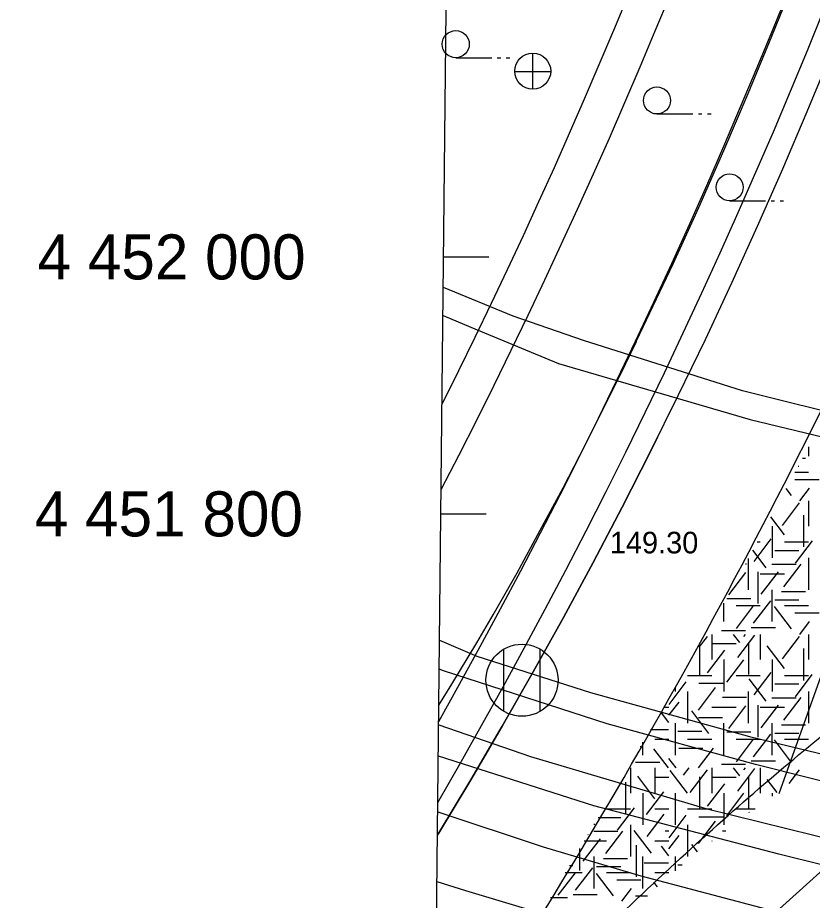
# Model space of a CAD drawing. Extents: x 419677 to 421689, y 4450851 to 4452923.
# Drawn here: x 420146.99 to 420191.07, y 4451964.28 to 4452013.28 of the extents above; entities that cross this region are included whole.
import ezdxf

# ---------------------------------------------------------------- set-up
doc = ezdxf.new("R2010")
doc.units = 0
for name, color, linetype in [('AA_HH', 7, 'Continuous'), ('Level 15', 7, 'Continuous'), ('Level 41', 7, 'Continuous'), ('Level 53', 7, 'Continuous'), ('Level 62', 7, 'Continuous'), ('Level 7', 7, 'Continuous')]:
    doc.layers.add(name, color=color, linetype=linetype)

msp = doc.modelspace()

# ---------------------------------------------------------------- linework, layer by layer
at = {"layer": 'AA_HH'}
for p, q in [((420171.29, 4452011.059), (420173.29, 4452011.059)), ((420173.59, 4452011.059), (420173.79, 4452011.059)), ((420174.09, 4452011.059), (420174.29, 4452011.059)), ((420175.574, 4452009.304), (420175.574, 4452011.304)), ((420174.554, 4452010.294), (420176.554, 4452010.294)), ((420182.45, 4452007.935), (420184.45, 4452007.935)), ((420184.75, 4452007.935), (420184.95, 4452007.935)), ((420185.25, 4452007.935), (420185.45, 4452007.935)), ((420186.481, 4452003.116), (420188.481, 4452003.116)), ((420188.781, 4452003.116), (420188.981, 4452003.116)), ((420189.281, 4452003.116), (420189.481, 4452003.116)), ((420170.62, 4452000), (420173.12, 4452000)), ((420170.469, 4451985.736), (420172.969, 4451985.736)), ((420173.965, 4451974.773), (420173.965, 4451978.234)), ((420175.965, 4451974.773), (420175.965, 4451978.234))]:
    msp.add_line(p, q, dxfattribs=at)
msp.add_lwpolyline([(420173.096, 4452234.536), (420705.284, 4452228.915), (420698.004, 4451534.891), (420165.768, 4451540.511)], close=True, dxfattribs=at)
for points in [[(420187.203, 4451992.557), (420178.373, 4451995.36), (420174.466, 4451996.716), (420170.602, 4451998.293)], [(420170.586, 4451996.757), (420172.131, 4451996.1), (420176.994, 4451994.079), (420187.618, 4451990.981)], [(420208.49, 4451987.848), (420200.392, 4451989.268), (420187.203, 4451992.557)], [(420187.618, 4451990.981), (420198.83, 4451988.282), (420204.042, 4451987.253), (420208.477, 4451986.632)], [(420170.395, 4451978.717), (420172.464, 4451977.845)], [(420172.464, 4451977.845), (420178.769, 4451975.819)], [(420178.769, 4451975.819), (420187.591, 4451973.382), (420198.769, 4451970.67), (420203.694, 4451969.685), (420203.855, 4451969.575), (420203.873, 4451969.498), (420203.829, 4451969.249), (420202.943, 4451968.135), (420202.702, 4451968.102), (420187.925, 4451971.818), (420179.685, 4451974.079), (420170.604, 4451977.031), (420170.378, 4451977.116)], [(420170.346, 4451974.034), (420175.443, 4451972.262), (420185.168, 4451969.381), (420195.648, 4451966.791), (420199.48, 4451965.936), (420200.521, 4451965.653), (420200.873, 4451965.482), (420200.86, 4451965.328), (420200.779, 4451965.109), (420200.125, 4451964.605), (420199.68, 4451964.413), (420199.276, 4451964.355), (420189.216, 4451966.84), (420178.959, 4451969.531)], [(420178.959, 4451969.531), (420170.327, 4451972.292)], [(420170.294, 4451969.192), (420176.139, 4451967.249), (420181.55, 4451965.648), (420190.183, 4451963.368), (420196.492, 4451961.996), (420196.577, 4451961.946), (420196.689, 4451961.78), (420196.627, 4451961.561), (420195.666, 4451959.622)], [(420172.68, 4451928.596), (420176.129, 4451935.418), (420177.785, 4451938.644), (420180.669, 4451943.689), (420183.638, 4451948.265), (420186.589, 4451952.666), (420190.119, 4451957.419), (420191.107, 4451958.75), (420191.136, 4451958.895), (420191.153, 4451959.063), (420191.123, 4451959.248), (420191.039, 4451959.379), (420190.981, 4451959.447), (420190.818, 4451959.577), (420182.51, 4451961.605), (420171.851, 4451964.82), (420170.254, 4451965.318)]]:
    msp.add_lwpolyline(points, dxfattribs=at)
for centre, radius in [((420171.29, 4452011.809), 0.75), ((420175.559, 4452010.312), 1), ((420182.45, 4452008.685), 0.75), ((420186.481, 4452003.866), 0.75), ((420174.965, 4451976.503), 2)]:
    msp.add_circle(centre, radius, dxfattribs=at)
at = {"layer": 'Level 15'}
msp.add_lwpolyline([(420240.251, 4451968.677), (420239.949, 4451966.602), (420239.949, 4451966.602), (420231.732, 4451917.739), (420240.801, 4451915.152), (420236.082, 4451892.337), (420229.855, 4451894.289), (420220.346, 4451839.788), (420214.729, 4451827.789), (420207.555, 4451825.12), (420146.986, 4451843.868), (420162.882, 4451888.718), (420178.991, 4451939.954), (420183.444, 4451958.583), (420204.023, 4451977.132), (420216.413, 4451977.263), (420240.251, 4451968.677)], dxfattribs=at)
at = {"layer": 'Level 41'}
for p, q in [((420190.866, 4451989.456), (420190.866, 4451988.935)), ((420190.531, 4451988.837), (420190.7, 4451988.837)), ((420190.105, 4451988.051), (420190.866, 4451988.051)), ((420190.284, 4451988.381), (420190.326, 4451988.381)), ((420190.102, 4451987.644), (420191.445, 4451987.644)), ((420189.919, 4451986.756), (420189.618, 4451987.151)), ((420190.385, 4451986.458), (420190.922, 4451987.164)), ((420189.413, 4451985.095), (420190.362, 4451986.345)), ((420190.866, 4451986.458), (420190.866, 4451985.06)), ((420189.52, 4451984.569), (420188.761, 4451985.567)), ((420190.584, 4451985.67), (420190.584, 4451983.903)), ((420188.852, 4451985.06), (420188.852, 4451983.293)), ((420187.842, 4451983.097), (420188.793, 4451984.346)), ((420188.008, 4451984.176), (420188.18, 4451984.176)), ((420189.523, 4451984.176), (420190.866, 4451984.176)), ((420190.133, 4451982.992), (420191.082, 4451984.242)), ((420188.508, 4451982.747), (420187.764, 4451983.725)), ((420188.983, 4451983.706), (420190.326, 4451983.706)), ((420187.509, 4451983.254), (420187.509, 4451981.526)), ((420190.866, 4451983.293), (420190.866, 4451981.526)), ((420187.355, 4451982.969), (420187.424, 4451982.969)), ((420188.823, 4451982.936), (420190.166, 4451982.936)), ((420189.493, 4451981.695), (420190.443, 4451982.945)), ((420186.43, 4451981.239), (420187.38, 4451982.489)), ((420188.041, 4451982.521), (420188.041, 4451980.753)), ((420188.18, 4451982.409), (420189.523, 4451982.409)), ((420188.241, 4451981.275), (420189.19, 4451982.524)), ((420188.852, 4451979.758), (420188.852, 4451981.526)), ((420189.357, 4451981.428), (420190.7, 4451981.428)), ((420186.166, 4451979.758), (420186.166, 4451980.772)), ((420186.32, 4451981.043), (420187.663, 4451981.043)), ((420187.816, 4451979.661), (420188.765, 4451980.911)), ((420188.983, 4451980.972), (420190.326, 4451980.972)), ((420186.837, 4451980.642), (420188.18, 4451980.642)), ((420186.856, 4451979.382), (420187.805, 4451980.631)), ((420189.919, 4451979.347), (420188.969, 4451980.596)), ((420189.523, 4451980.642), (420190.866, 4451980.642)), ((420190.102, 4451980.235), (420191.445, 4451980.235)), ((420190.385, 4451979.049), (420190.922, 4451979.755)), ((420186.027, 4451979.255), (420187.37, 4451979.255)), ((420187.679, 4451979.43), (420189.022, 4451979.43)), ((420184.796, 4451978.34), (420185.248, 4451978.936)), ((420185.494, 4451979.049), (420185.494, 4451977.651)), ((420187.043, 4451978.597), (420186.699, 4451979.049)), ((420186.936, 4451977.755), (420187.886, 4451979.005)), ((420187.269, 4451978.929), (420187.36, 4451979.049)), ((420188.18, 4451979.049), (420188.18, 4451977.651)), ((420189.413, 4451977.686), (420190.362, 4451978.936)), ((420190.866, 4451979.049), (420190.866, 4451977.651)), ((420184.819, 4451978.38), (420184.819, 4451976.78)), ((420185.494, 4451978.535), (420186.837, 4451978.535)), ((420187.536, 4451978.582), (420187.536, 4451976.815)), ((420189.52, 4451977.16), (420188.571, 4451978.409)), ((420190.584, 4451978.261), (420190.584, 4451976.494)), ((420185.259, 4451976.914), (420186.208, 4451978.164)), ((420186.166, 4451977.651), (420186.166, 4451975.884)), ((420186.325, 4451976.389), (420187.274, 4451977.639)), ((420188.852, 4451977.651), (420188.852, 4451975.884)), ((420184.151, 4451976.767), (420185.494, 4451976.767)), ((420186.837, 4451976.767), (420188.18, 4451976.767)), ((420187.842, 4451975.688), (420188.793, 4451976.937)), ((420189.523, 4451976.767), (420190.866, 4451976.767)), ((420190.133, 4451975.583), (420191.069, 4451976.815)), ((420183.128, 4451975.163), (420184.077, 4451976.412)), ((420184.775, 4451976.333), (420186.118, 4451976.333)), ((420188.508, 4451975.338), (420187.558, 4451976.587)), ((420188.983, 4451976.297), (420190.326, 4451976.297)), ((420183.48, 4451975.884), (420183.48, 4451976.123)), ((420184.151, 4451975.884), (420184.151, 4451974.117)), ((420184.753, 4451974.846), (420185.702, 4451976.096)), ((420187.509, 4451975.884), (420187.509, 4451974.117)), ((420190.866, 4451975.884), (420190.866, 4451974.117)), ((420183.118, 4451974.554), (420183.677, 4451975.29)), ((420186.081, 4451975.56), (420187.424, 4451975.56)), ((420188.823, 4451975.527), (420190.166, 4451975.527)), ((420189.493, 4451974.286), (420190.443, 4451975.536)), ((420182.813, 4451975), (420183.118, 4451975)), ((420185.338, 4451973.549), (420184.389, 4451974.799)), ((420185.494, 4451975), (420186.837, 4451975)), ((420186.43, 4451973.83), (420187.38, 4451975.08)), ((420188.041, 4451975.112), (420188.041, 4451973.344)), ((420188.18, 4451975), (420189.523, 4451975)), ((420188.241, 4451973.866), (420189.19, 4451975.115)), ((420183.118, 4451974.16), (420182.712, 4451974.694)), ((420184.748, 4451974.44), (420186.091, 4451974.44)), ((420183.48, 4451972.349), (420183.48, 4451974.117)), ((420186.166, 4451972.349), (420186.166, 4451974.117)), ((420188.852, 4451972.349), (420188.852, 4451974.117)), ((420189.357, 4451974.019), (420190.7, 4451974.019)), ((420182.086, 4451973.774), (420183.084, 4451973.774)), ((420183.603, 4451973.668), (420184.946, 4451973.668)), ((420186.32, 4451973.634), (420187.663, 4451973.634)), ((420187.816, 4451972.252), (420188.765, 4451973.502)), ((420188.983, 4451973.563), (420190.326, 4451973.563)), ((420181.523, 4451972.826), (420181.566, 4451972.826)), ((420181.659, 4451972.349), (420181.659, 4451973.055)), ((420182.33, 4451973.233), (420183.118, 4451973.233)), ((420184.151, 4451973.233), (420185.494, 4451973.233)), ((420186.837, 4451973.233), (420188.18, 4451973.233)), ((420186.856, 4451971.973), (420187.805, 4451973.222)), ((420189.919, 4451971.938), (420188.969, 4451973.187)), ((420189.523, 4451973.233), (420190.866, 4451973.233)), ((420183.089, 4451971.64), (420182.287, 4451972.696)), ((420183.657, 4451972.722), (420184.999, 4451972.722)), ((420184.765, 4451971.64), (420185.594, 4451972.731)), ((420181.262, 4451971.952), (420182.605, 4451971.952)), ((420183.512, 4451971.64), (420183.118, 4451972.158)), ((420186.027, 4451971.846), (420187.37, 4451971.846)), ((420187.679, 4451972.021), (420189.022, 4451972.021)), ((420180.987, 4451971.64), (420180.987, 4451970.242)), ((420182.33, 4451971.64), (420182.33, 4451970.242)), ((420182.33, 4451971.64), (420182.33, 4451970.242)), ((420184.139, 4451970.242), (420183.19, 4451971.492)), ((420183.928, 4451971.223), (420184.245, 4451971.64)), ((420184.299, 4451970.277), (420185.248, 4451971.527)), ((420185.494, 4451971.64), (420185.494, 4451970.242)), ((420187.043, 4451971.188), (420186.699, 4451971.64)), ((420186.936, 4451970.346), (420187.886, 4451971.596)), ((420187.269, 4451971.52), (420187.36, 4451971.64)), ((420188.18, 4451971.64), (420188.18, 4451970.242)), ((420189.786, 4451970.769), (420190.362, 4451971.527)), ((420182.331, 4451969.926), (420181.382, 4451971.175)), ((420182.33, 4451971.126), (420183.118, 4451971.126)), ((420184.819, 4451971.138), (420184.819, 4451969.371)), ((420185.494, 4451971.126), (420186.837, 4451971.126)), ((420187.536, 4451971.173), (420187.536, 4451969.406)), ((420189.122, 4451970.274), (420188.571, 4451971)), ((420180.705, 4451970.852), (420180.705, 4451969.085)), ((420185.259, 4451969.505), (420186.208, 4451970.755)), ((420181.659, 4451970.242), (420181.659, 4451968.475)), ((420181.659, 4451970.242), (420181.659, 4451968.475)), ((420181.879, 4451969.049), (420182.828, 4451970.299)), ((420183.48, 4451968.475), (420183.48, 4451970.242)), ((420186.166, 4451970.242), (420186.166, 4451968.475)), ((420186.325, 4451968.98), (420187.274, 4451970.23)), ((420188.852, 4451970.242), (420188.852, 4451970.073)), ((420180.254, 4451968.174), (420181.203, 4451969.424)), ((420179.644, 4451969.358), (420180.987, 4451969.358)), ((420181.905, 4451967.823), (420182.855, 4451969.072)), ((420182.33, 4451969.358), (420183.118, 4451969.358)), ((420183.128, 4451967.754), (420184.077, 4451969.003)), ((420184.151, 4451969.358), (420185.494, 4451969.358)), ((420184.775, 4451968.924), (420186.118, 4451968.924)), ((420186.837, 4451969.358), (420187.891, 4451969.358)), ((420187.591, 4451969.135), (420187.558, 4451969.178)), ((420178.973, 4451968.53), (420178.973, 4451968.475)), ((420179.186, 4451968.888), (420180.447, 4451968.888)), ((420180.987, 4451968.475), (420180.987, 4451966.708)), ((420184.151, 4451968.475), (420184.151, 4451966.708)), ((420184.753, 4451967.437), (420185.702, 4451968.687)), ((420178.629, 4451967.929), (420178.622, 4451967.938)), ((420178.944, 4451968.118), (420180.287, 4451968.118)), ((420179.614, 4451966.877), (420180.564, 4451968.127)), ((420182.144, 4451966.911), (420181.195, 4451968.16)), ((420182.914, 4451968.151), (420183.118, 4451968.151)), ((420186.081, 4451968.151), (420186.269, 4451968.151)), ((420178.362, 4451966.457), (420179.311, 4451967.706)), ((420178.416, 4451967.591), (420179.644, 4451967.591)), ((420182.33, 4451967.591), (420183.118, 4451967.591)), ((420183.118, 4451967.145), (420183.677, 4451967.881)), ((420185.494, 4451967.591), (420185.517, 4451967.591)), ((420178.162, 4451967.163), (420178.162, 4451965.935)), ((420181.305, 4451967.353), (420181.305, 4451965.585)), ((420183.118, 4451966.751), (420182.712, 4451967.285)), ((420184.699, 4451966.982), (420184.389, 4451967.39)), ((420184.748, 4451967.031), (420184.765, 4451967.031)), ((420178.973, 4451964.94), (420178.973, 4451966.708)), ((420179.478, 4451966.61), (420180.821, 4451966.61)), ((420181.659, 4451964.94), (420181.659, 4451966.708)), ((420183.48, 4451965.925), (420183.48, 4451966.708)), ((420177.605, 4451966.225), (420177.784, 4451966.225)), ((420177.937, 4451964.843), (420178.886, 4451966.093)), ((420179.104, 4451966.154), (420180.447, 4451966.154)), ((420181.741, 4451966.365), (420183.084, 4451966.365)), ((420183.603, 4451966.259), (420183.856, 4451966.259)), ((420176.977, 4451964.564), (420177.926, 4451965.813)), ((420177.367, 4451965.824), (420178.301, 4451965.824)), ((420180.04, 4451964.529), (420179.09, 4451965.778)), ((420179.644, 4451965.824), (420180.987, 4451965.824)), ((420182.33, 4451965.824), (420183.118, 4451965.824)), ((420180.223, 4451965.417), (420181.566, 4451965.417)), ((420182.478, 4451965.035), (420182.287, 4451965.287)), ((420177.8, 4451964.612), (420179.143, 4451964.612)), ((420180.506, 4451964.231), (420181.043, 4451964.937)), ((420181.262, 4451964.543), (420181.925, 4451964.543)), ((420176.544, 4451964.437), (420177.491, 4451964.437))]:
    msp.add_line(p, q, dxfattribs=at)
at = {"layer": 'Level 53'}
for points in [[(420170.357, 4451975.119), (420171.08, 4451976.28), (420172.46, 4451978.58), (420173.37, 4451980.14), (420174.69, 4451982.47), (420175.98, 4451984.83), (420177.24, 4451987.19), (420178.48, 4451989.58), (420179.68, 4451991.97), (420180.39, 4451993.39), (420181.88, 4451996.5), (420183.35, 4451999.61), (420184.77, 4452002.75), (420186.16, 4452005.9), (420187.52, 4452009.07), (420188.83, 4452012.25), (420190.11, 4452015.45)], [(420170.281, 4451967.921), (420170.33, 4451968), (420172.12, 4451970.97), (420173.87, 4451973.95), (420175.58, 4451976.96), (420177.26, 4451979.99), (420178.91, 4451983.04), (420180.52, 4451986.11), (420182.09, 4451989.19), (420183.63, 4451992.3), (420185.14, 4451995.42), (420186.6, 4451998.56), (420188.03, 4452001.71), (420189.43, 4452004.88), (420190.79, 4452008.07), (420192.11, 4452011.27), (420193.39, 4452014.49)], [(420170.357, 4451975.119), (420171.08, 4451976.28), (420172.46, 4451978.58), (420173.37, 4451980.14), (420174.69, 4451982.47), (420175.98, 4451984.83), (420177.24, 4451987.19), (420178.48, 4451989.58), (420179.68, 4451991.97), (420180.39, 4451993.39), (420181.31, 4451995.3)], [(420182.49, 4451989.99), (420182.09, 4451989.19), (420180.52, 4451986.11), (420178.91, 4451983.04), (420177.26, 4451979.99), (420175.58, 4451976.96), (420173.87, 4451973.95), (420172.12, 4451970.97), (420170.33, 4451968), (420170.281, 4451967.921)]]:
    msp.add_lwpolyline(points, dxfattribs=at)
at = {"layer": 'Level 62'}
msp.add_line((420189.23, 4451970.21), (420197.829, 4451994.363), dxfattribs=at)
for centre, radius, start, end in [((419869.259, 4452142.553), 336.876, 333.42072, 355.99452), ((419871.682, 4452142.243), 344.876, 329.98199, 355.99254), ((419876.283, 4452147.722), 351.876, 327.39987, 336.19063)]:
    msp.add_arc(centre, radius, start, end, dxfattribs=at)
msp.add_open_spline([(420174.141, 4451957.431), (420207.126, 4451990.277), (420233.269, 4451982.965), (420233.274, 4451982.982)], degree=2, dxfattribs=at)
at = {"layer": 'Level 7'}
for radius, start, end in [(337.876, 332.60484, 356.02111), (343.876, 330.68805, 355.99512)]:
    msp.add_arc((419870.498, 4452142.553), radius, start, end, dxfattribs=at)

# ---------------------------------------------------------------- texts
at = {"layer": 'AA_HH'}
for s, height, p in [('4 452 000', 2.5, (420148.088, 4451998.75)), ('4 451 800', 2.5, (420147.938, 4451984.486)), ('149.30 ', 1.2, (420179.837, 4451983.542))]:
    msp.add_text(s, height=height, dxfattribs=at).set_placement(p)

doc.saveas('drawing.dxf')
